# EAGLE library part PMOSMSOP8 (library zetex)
MOS FET
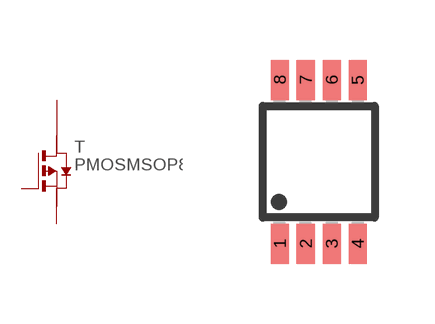
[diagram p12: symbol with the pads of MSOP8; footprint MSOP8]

Designator prefix T

## PMOSMSOP8 (OC_FARNELL: 1412091; OC_NEWARK: unknown)  [MSOP8]
1  S  pas
2  S1  pas
3  S2  pas
4  G  pas
5  D  pas
6  D1  pas
7  D2  pas
8  D3  pas

## Footprint MSOP8 (pad centres in mm)
Micro Small Outline Package
smd 0.45 x 1: 1 -0.975,-2.05; 2 -0.325,-2.05; 3 0.325,-2.05; 4 0.975,-2.05; 5 0.975,2.05; 6 0.325,2.05; 7 -0.325,2.05; 8 -0.975,2.05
